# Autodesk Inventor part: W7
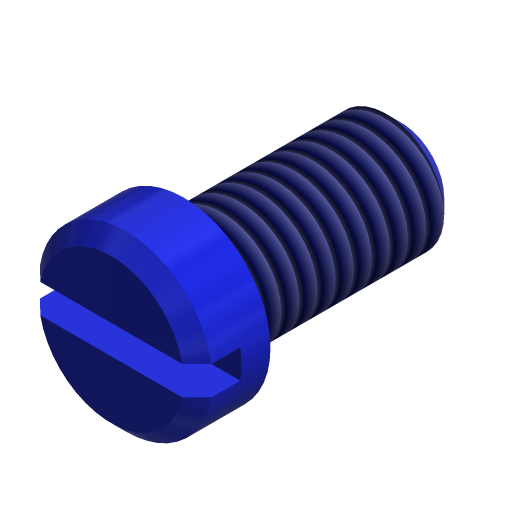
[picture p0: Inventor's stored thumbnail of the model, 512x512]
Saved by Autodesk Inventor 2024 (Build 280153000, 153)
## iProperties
Company: ATC
Shininess: 0.0
Length Units: 11269
Angle Units: 11279
Time Units: 11290
Mass Units: 11283
Length Display Precision: 3
Angle Display Precision: 2
Compacted: True
Created: 2023-03
Part Number: W7
Document SubType Name: Modeling
Designer: Andrzej Jaskulski
Material: Kurs-AJ
Density: 1 g/cm^3
Appearance: Niebieska — farba ścienna — lśniąca
Checked By: A.J.
Engr Approved By: Andrzej Jaskulski
Mfg Approved By: Andrzej Jaskulski
Authority: A.J.
Density: 0.0
Volumn: 0.0
Area: 0.0
PropertySet Name: Model Information
Control State: 0
Master: False
Checked Out: False
Title: A.J.: Kurs R2024-MEP
Author: Andrzej Jaskulski
Revision Number: 1/24
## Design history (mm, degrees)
node "Extrusion1" dims "d1" = 15, "d2" = 0
  sketch "Sketch1"
    geometry: C1 r 4 at (0, 0)
    constraints: 1 centre point, 1 other
    dimensions: "d0" = 8 diameter of C1
node "Extrusion2" dims "d4" = 5, "d5" = 0
  sketch "Sketch2"
    geometry: C1 r 4 at (0, 0) reference; C2 r 6 at (0, 0)
    constraints: 1 centre point, 1 coincident
    dimensions: "d3" = 12 diameter of C2
node "Chamfer1" dims "d6" = 1, "d7" = 1, "d39" = 45 deg
workplane "Work Plane2"
node "Extrusion3" dims "d11" = 5, "d12" = 0
  sketch "Sketch3"
    geometry: L1 (-1, 5)-(1, 5); L2 (1, 5)-(1, 2); L3 (1, 2)-(-1, 2); L4 (-1, 2)-(-1, 5); L5 (0, 2)-(0, 8)
    constraints: 10 end point, 3 parallel, 1 horizontal, 1 midpoint, 1 perpendicular
    dimensions: "d8" = 3 distance of L1.end L2.end; "d10" = 1 distance between parallel lines of L2 L5
thread "Thread1" dims "d37" = 10, "d38" = 0
node "Bryła1"
node "Korpusy bryłowe"
node "Korpusy powierzchniowe"
other parameters: "p" = 1.25 [user parameter], "de" = 8 [user parameter], "de1" = 6.647 [user parameter], "de2" = 7.188 [user parameter]
